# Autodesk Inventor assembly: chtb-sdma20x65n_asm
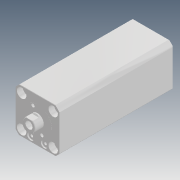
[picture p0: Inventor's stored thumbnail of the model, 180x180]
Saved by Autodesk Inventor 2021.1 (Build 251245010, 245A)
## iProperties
Created: 2018-05
Part Number: chtb-sdma20x65n_asm
Description: STEP AP214
Document SubType Name: Assembly
Designer: user
Title: chtb-sdma20x65n_asm.STEP
Revision Number: ÈÎºÎ
Sending System: SolidWorks 2016
Preprocessor: SwSTEP 2.0
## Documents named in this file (5)
- D:\Vault_2016\Projekty\Clamptek\Hydraulic\CHTB\CHTB-20\Inventor\CHTB-SDMA20x65N\chtb-sdma20x65n_asm.iam
- D:\Vault_2016\Projekty\Clamptek\Hydraulic\CHTB\CHTB-20\Inventor\CHTB-SDMA20x65N\CHTB-SDMA20X65NBT.ipt
- D:\Vault_2016\Projekty\Clamptek\Hydraulic\CHTB\CHTB-20\Inventor\CHTB-SDMA20x65N\CHTB-SDMA20X65NHSG.ipt
- D:\Vault_2016\Projekty\Clamptek\Hydraulic\CHTB\CHTB-20\Inventor\CHTB-SDMA20x65N\QG_3.ipt
- D:\Vault_2016\Projekty\Clamptek\Hydraulic\CHTB\CHTB-20\Inventor\CHTB-SDMA20x65N\socket set screw flat point_iso_ISO 4026 - M5 x 5-N.ipt
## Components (5 placed, 5 different names)
1. CHTB-SDMA20X65NBT_1
2. CHTB-SDMA20X65NHSG_2
3. QG_3_3
4. socket set screw flat point_iso_ISO 4026 - M5 x 5-N_4
5. socket set screw flat point_iso_ISO 4026 - M5 x 5-N_5
